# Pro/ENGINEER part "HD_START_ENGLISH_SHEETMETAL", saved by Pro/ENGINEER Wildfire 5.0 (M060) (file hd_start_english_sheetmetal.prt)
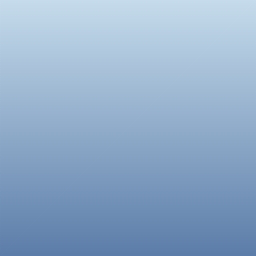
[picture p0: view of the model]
Units: Inch lbm Second (Pro/E Default); INCH, POUND, SECS
Materials in the file: DEFAULT

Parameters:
  DRW_UNITS = "ENGLISH"
  TOL_NAME = "INCHES"
  SUR = "250"
  PTC_MATERIAL_NAME = "DEFAULT"

Other parameters: SMT_THICKNESS

Other named items: CS_DEF, PT_ORIG, SIDE, TOP, FRONT

Layers: ANNOT, AXES, COSMETIC, CS, CURVES, DATUMS, DEF_CS, DEF_DATUMS, GEOM_CRVS, GEOM_DATUMS, GEOM_PNTS, PTS, SURFS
